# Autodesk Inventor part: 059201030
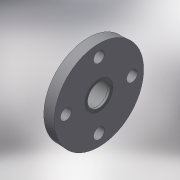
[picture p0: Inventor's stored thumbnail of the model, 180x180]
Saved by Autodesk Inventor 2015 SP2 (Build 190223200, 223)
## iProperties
Created: 2017-10
Part Number: 059201030
Material: Generic
Description: PLASSON THR. FIXED FLANGE PVC 3"
Document SubType Name: Modeling
Designer: KIM
Density: 1 g/cm^3
Appearance: Default
Author: KIM
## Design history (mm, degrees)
derived "059201.ipt"
feature "Solid1::059201.ipt"
tag "TaggingFeature1"
body "Solid1"
other parameters: "d0" = 54, "d3" = 198, "d14" = 18, "d16" = 54, "d17" = 0, "d19" = 360 deg, "d21" = 33, "d22" = 84.926, "d23" = 80.6797, "d25" = 0.84926, "d26" = 1, "d27" = 1, "d28" = 1, "d29" = 1, "d30" = 1, "d31" = 1, "d32" = 0.4, "d33" = 0, "d35" = 101.9112, "H_" = 54, "S_" = 18, "lt_" = 33, "G_" = 84.926
